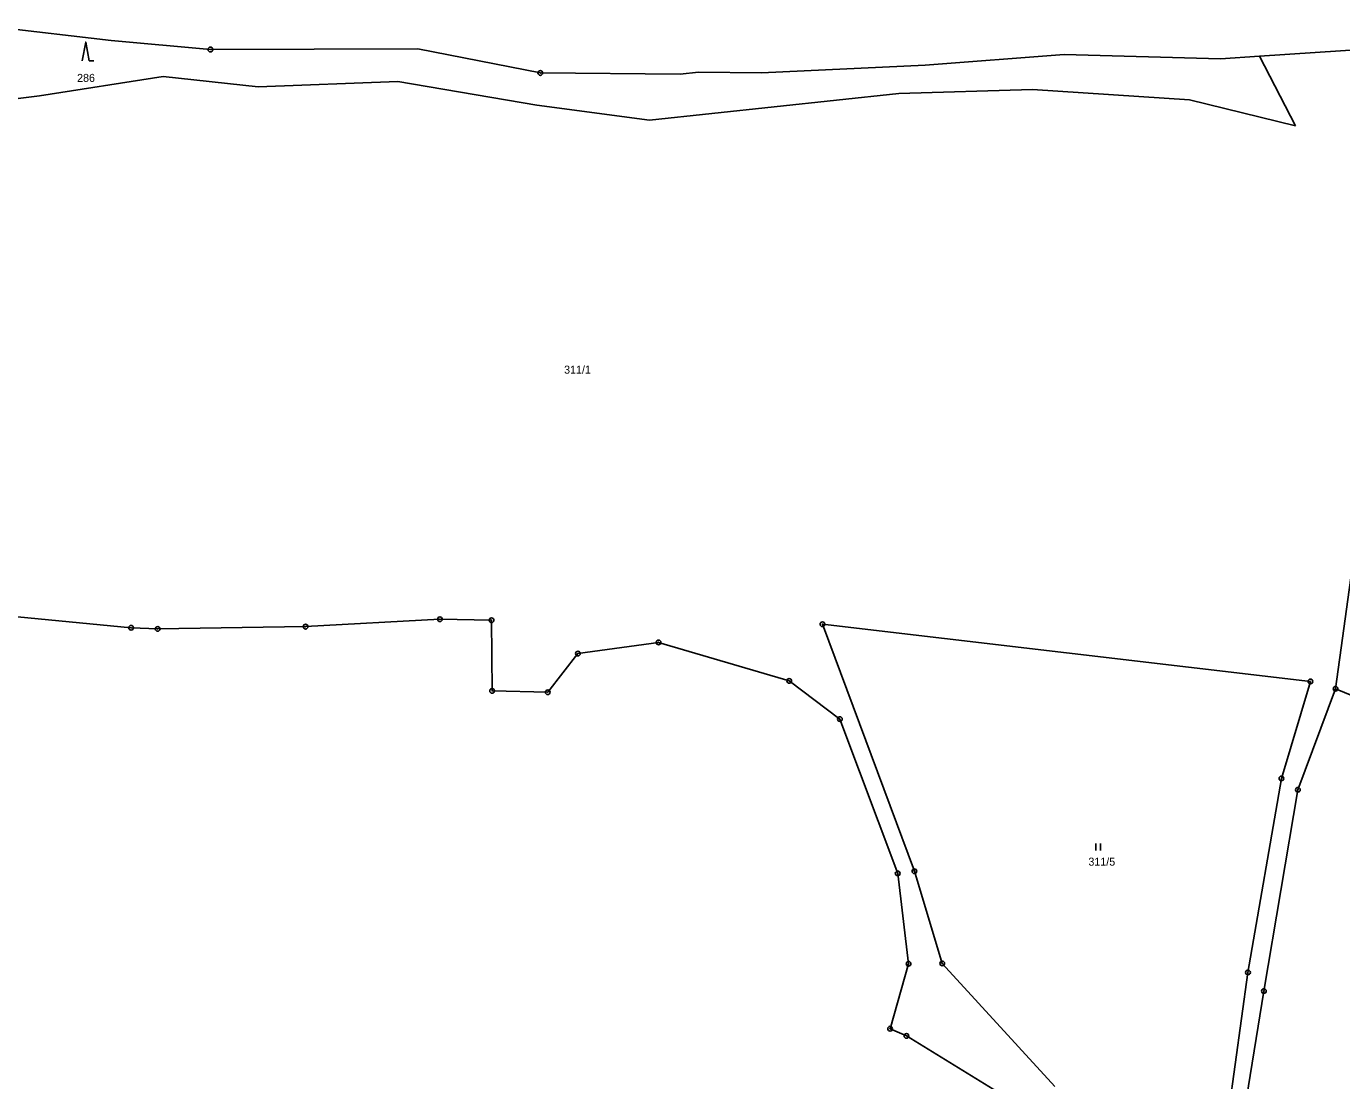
# Model space of a CAD drawing. Extents: x -754970 to -752637, y -970569 to -968179.
# Drawn here: x -753912.9 to -753633.5, y -968596.7 to -968372.6 of the extents above; entities that cross this region are included whole.
import ezdxf
from ezdxf.enums import TextEntityAlignment as Align

# ---------------------------------------------------------------- set-up
doc = ezdxf.new("R2010")
doc.units = 0
doc.header["$LTSCALE"] = 0.68
for name, color, linetype, lineweight in [('1', 7, 'Continuous', 25), ('3', 7, 'Continuous', 25), ('8', 7, 'Continuous', 25)]:
    doc.layers.add(name, color=color, linetype=linetype, lineweight=lineweight)
doc.layers.add('2', color=7, linetype='Continuous')

msp = doc.modelspace()

# ---------------------------------------------------------------- linework, layer by layer
at = {"layer": '1'}
for p, q in [((-753920.58, -968372.64), (-753894.83, -968375.66)), ((-753894.83, -968375.66), (-753873.77, -968377.57)), ((-753873.77, -968377.57), (-753829.68, -968377.45)), ((-753829.68, -968377.45), (-753803.69, -968382.56)), ((-753721.93, -968380.91), (-753692.41, -968378.62)), ((-753692.41, -968378.62), (-753659.23, -968379.57)), ((-753650.97, -968379.02), (-753627.32, -968377.45)), ((-753756.72, -968382.54), (-753721.93, -968380.91)), ((-753659.23, -968379.57), (-753650.97, -968379.02)), ((-753650.97, -968379.02), (-753643.27, -968393.82)), ((-753863.64, -968385.52), (-753833.96, -968384.35)), ((-753833.96, -968384.35), (-753804.41, -968389.38)), ((-753803.69, -968382.56), (-753774.01, -968382.84)), ((-753774.01, -968382.84), (-753770.07, -968382.41)), ((-753770.07, -968382.41), (-753756.72, -968382.54)), ((-753780.5, -968392.55), (-753727.52, -968386.95)), ((-753727.52, -968386.95), (-753699.14, -968386.07)), ((-753699.14, -968386.07), (-753665.79, -968388.28)), ((-753930.19, -968389.85), (-753910.07, -968387.44)), ((-753804.41, -968389.38), (-753780.5, -968392.55)), ((-753665.79, -968388.28), (-753643.27, -968393.82)), ((-753634.77, -968513.39), (-753630.99, -968485.75)), ((-753924.64, -968497.14), (-753890.6, -968500.44)), ((-753853.55, -968500.2), (-753825.02, -968498.63)), ((-753825.02, -968498.63), (-753814.06, -968498.84)), ((-753814.06, -968498.84), (-753813.93, -968513.85)), ((-753890.6, -968500.44), (-753884.97, -968500.69)), ((-753884.97, -968500.69), (-753853.55, -968500.2)), ((-753743.77, -968499.68), (-753724.24, -968552.17)), ((-753743.77, -968499.68), (-753640.12, -968511.85)), ((-753795.7, -968505.92), (-753778.57, -968503.54)), ((-753778.57, -968503.54), (-753750.83, -968511.73)), ((-753802.12, -968514.12), (-753795.7, -968505.92)), ((-753750.83, -968511.73), (-753740.06, -968519.85)), ((-753640.12, -968511.85), (-753646.29, -968532.46)), ((-753813.93, -968513.85), (-753802.12, -968514.12)), ((-753634.77, -968513.39), (-753642.77, -968534.87)), ((-753634.77, -968513.39), (-753602.68, -968526.65)), ((-753740.06, -968519.85), (-753727.79, -968552.63)), ((-753646.29, -968532.46), (-753653.38, -968573.68)), ((-753642.77, -968534.87), (-753650, -968577.63)), ((-753727.79, -968552.63), (-753725.47, -968571.81)), ((-753724.24, -968552.17), (-753718.31, -968571.75)), ((-753725.47, -968571.81), (-753729.4, -968585.62)), ((-753718.31, -968571.75), (-753694.38, -968597.91)), ((-753657.81, -968605.58), (-753653.38, -968573.68)), ((-753650, -968577.63), (-753654.36, -968604.55)), ((-753729.4, -968585.62), (-753725.93, -968587.15)), ((-753725.93, -968587.15), (-753699.79, -968603.19))]:
    msp.add_line(p, q, dxfattribs=at)
msp.add_lwpolyline([(-753910.07, -968387.44), (-753883.81, -968383.34), (-753863.64, -968385.52)], dxfattribs=at)
at = {"layer": '3'}
for p, q in [((-753899.51, -968379.99), (-753898.514, -968379.99)), ((-753685.711, -968547.76), (-753685.711, -968546.26)), ((-753684.71, -968547.76), (-753684.71, -968546.26))]:
    msp.add_line(p, q, dxfattribs=at)
msp.add_lwpolyline([(-753899.51, -968379.99), (-753900.26, -968375.99), (-753901.01, -968379.99)], dxfattribs=at)
at = {"layer": '8'}
for centre, radius in [((-753873.77, -968377.5699), 0.5), ((-753873.77, -968377.5699), 0.0303), ((-753803.69, -968382.5599), 0.5), ((-753803.69, -968382.5599), 0.0303), ((-753825.02, -968498.6299), 0.5), ((-753825.02, -968498.6299), 0.0303), ((-753814.06, -968498.8399), 0.5), ((-753814.06, -968498.8399), 0.0303), ((-753890.6, -968500.4399), 0.5), ((-753890.6, -968500.4399), 0.0303), ((-753884.97, -968500.6899), 0.5), ((-753884.97, -968500.6899), 0.0303), ((-753853.55, -968500.1999), 0.5), ((-753853.55, -968500.1999), 0.0303), ((-753743.77, -968499.6799), 0.5), ((-753743.77, -968499.6799), 0.0303), ((-753778.57, -968503.5399), 0.5), ((-753778.57, -968503.5399), 0.0303), ((-753795.7, -968505.9199), 0.5), ((-753795.7, -968505.9199), 0.0303), ((-753750.83, -968511.7299), 0.5), ((-753750.83, -968511.7299), 0.0303), ((-753640.12, -968511.8499), 0.5), ((-753640.12, -968511.8499), 0.0303), ((-753634.77, -968513.3899), 0.5), ((-753813.93, -968513.8499), 0.5), ((-753813.93, -968513.8499), 0.0303), ((-753802.12, -968514.1199), 0.5), ((-753802.12, -968514.1199), 0.0303), ((-753634.77, -968513.3899), 0.0303), ((-753740.06, -968519.8499), 0.5), ((-753740.06, -968519.8499), 0.0303), ((-753646.29, -968532.4599), 0.5), ((-753646.29, -968532.4599), 0.0303), ((-753642.77, -968534.8699), 0.5), ((-753642.77, -968534.8699), 0.0303), ((-753727.79, -968552.6299), 0.5), ((-753724.24, -968552.1699), 0.5), ((-753727.79, -968552.6299), 0.0303), ((-753724.24, -968552.1699), 0.0303), ((-753725.47, -968571.8099), 0.5), ((-753718.31, -968571.7499), 0.5), ((-753725.47, -968571.8099), 0.0303), ((-753718.31, -968571.7499), 0.0303), ((-753653.38, -968573.6799), 0.5), ((-753653.38, -968573.6799), 0.0303), ((-753650, -968577.6299), 0.5), ((-753650, -968577.6299), 0.0303), ((-753729.4, -968585.6199), 0.5), ((-753729.4, -968585.6199), 0.0303), ((-753725.93, -968587.1499), 0.5), ((-753725.93, -968587.1499), 0.0303)]:
    msp.add_circle(centre, radius, dxfattribs=at)

# ---------------------------------------------------------------- texts
at = {"layer": '2'}
for s, p in [('286', (-753900.189, -968384.455)), ('311/1', (-753795.8, -968446.445))]:
    msp.add_text(s, height=1.7, dxfattribs=at).set_placement(p, align=Align.CENTER)
msp.add_text('311/5', height=1.7, dxfattribs=at).set_placement((-753687.28, -968550.985))

doc.saveas('drawing.dxf')
